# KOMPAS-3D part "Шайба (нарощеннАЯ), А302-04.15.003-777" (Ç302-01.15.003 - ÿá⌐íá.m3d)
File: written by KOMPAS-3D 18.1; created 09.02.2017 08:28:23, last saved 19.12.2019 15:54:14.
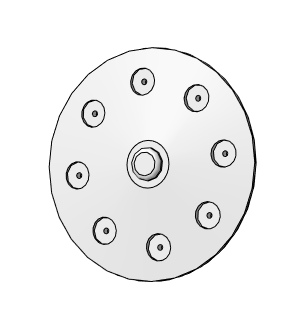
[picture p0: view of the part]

Document properties: Автор: Милов; Организация: Милов; Полное имя файла: D:\Мембранные насосы\Мембранный электропривод\А302-00.00.000 - ASTRA-302 (МЭ200)\3Д ПВХ\А302-01.15.003 - Шайба.m3d

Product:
- Part/product: Шайба (нарощеннАЯ)  | designation А302-04.15.003-777
    Материал: Полипропилен  ГОСТ 26996-86 (density 900 kg/m3)
    Масса: 0.433016
    Раздел спецификации: Детали
    Форматы листов документа: A4
    source file: ..\А302-04.00.000 - Мембранный насос ASTRA-302-PP\А302-04.15.003-777 - Шайба.cdw
- Part/product: Шайба  | designation А302-05.15.003
    Материал: Поливинилхлорид (density 0 kg/m3)
    Раздел спецификации: Детали
    Форматы листов документа: A4
    source file: ..\А302-04.00.000 - Мембранный насос ASTRA-302-PP\А302-04.15.003 - Шайба.cdw, ..\Чертежи ПВХ\А302-02.15.003 - Шайба.cdw, ..\Чертежи Полипропилен\А302-03.15.003 - Шайба.cdw
- Part/product: Шайба  | designation А302-01.15.003
    Масса: 0.292092
    Раздел спецификации: Детали
    Форматы листов документа: A4
- Part/product: Шайба  | designation А302-03.15.003
    Материал: Полипропилен  ГОСТ 26996-86 (density 900 kg/m3)
    Масса: 0.28231
    Раздел спецификации: Детали
    Форматы листов документа: A4
    source file: ..\Чертежи Полипропилен\А302-03.15.003 - Шайба.cdw
- Part/product: Шайба  | designation А302-02.15.003
    Материал: Полипропилен  ГОСТ 26996-86 (density 900 kg/m3)
    Масса: 0.251914
    Раздел спецификации: Детали
    Форматы листов документа: A4
- Part/product: Шайба  | designation А302-04.15.003
    Материал: Полипропилен  ГОСТ 26996-86 (density 900 kg/m3)
    Масса: 0.247573
    Раздел спецификации: Детали
    Форматы листов документа: A4

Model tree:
1. Эскиз:7
2. Операция вращения:1
     Угол 1 = 360
3. Скругление:16  (with: Операция вращения:1)
     Радиус = 4
4. Отверстие:1  (with: Операция вращения:1)
     Глубина выреза = 15; Диаметр отверстия = 7.8; Угол конуса торца = 118
5. Эскиз:22  (with: Операция вращения:1, Отверстие:1)
6. Отверстие:2
     Глубина выреза = 9; Диаметр отверстия = 6; Угол конуса торца = 118; Координата Y = -50
7. Массив по концентрической сетке:1  (with: Отверстие:2, Эскиз:22)  (4 pattern instances)
     Шаг 2 = 360
8. Эскиз:23
9. Отверстие:3
     Глубина выреза = 15; Диаметр отверстия = 5; Угол конуса торца = 118; Координата Y = 70
10. Эскиз:24  (with: Операция вращения:1)
11. Вырезать элемент выдавливания:3
     Расстояние 1 = 7.5
12. Массив по концентрической сетке:2  (with: Отверстие:3, Эскиз:23, Вырезать элемент выдавливания:3, Эскиз:24)  (6 pattern instances)
     Шаг 2 = 360
13. Фаска:1  (with: Отверстие:1)
     Угол = 45; Длина 1 = 1; Длина 2 = 1
14. Эскиз:25  (with: Операция вращения:1, Отверстие:1)
15. Операция выдавливания:1
     Расстояние 1 = 11
16. Условное изображение резьбы:1  (with: Операция выдавливания:1)
     Длина резьбы = 11; Шаг резьбы = 1.814; Номинальный диаметр резьбы = 20.955
17. Подгонка:1  (with: Операция выдавливания:1)
18. Фаска:2  (with: Операция выдавливания:1)  (labels: Полипропилен  ГОСТ 26996-86)
     Угол = 45; Длина 1 = 8; Длина 2 = 8
19. Скругление:17  (with: Операция вращения:1)
     Радиус = 4
20. Эскиз:26  (with: Операция вращения:1, Скругление:16)
21. Элемент выдавливания:1
     Расстояние 2 = 10
22. Скругление:18  (with: Элемент выдавливания:1)  (labels: Полипропилен  ГОСТ 26996-86)
     Радиус = 3
23. Отверстие:3  (with: Эскиз:23)
24. Вырезать элемент выдавливания:3  (with: Эскиз:23, Эскиз:24, Отверстие:3)  (1 pattern instances)
     N 1 = 1; Шаг 1 = 10; Шаг 2 = 360; Номер 1 = 1
25. Эскиз:27  (with: Операция вращения:1, Скругление:16)
26. Элемент выдавливания:3
     Расстояние 2 = 1
27. Эскиз:28  (with: Элемент выдавливания:3)
28. Элемент выдавливания:4
     Толщина стенки 1 = 2; Расстояние 1 = 1
29. Скругление:19  (with: Элемент выдавливания:4)
     Радиус = 1
30. Фаска:3  (with: Элемент выдавливания:3, Скругление:16)
     Угол = 15; Длина 1 = 13; Длина 2 = 3.48334
31. Скругление:20  (with: Фаска:3)
     Радиус = 2
32. Скругление:21  (with: Элемент выдавливания:4)  (labels: Полипропилен  ГОСТ 26996-86)
     Радиус = 0.5
33. Точка:1  (with: Операция вращения:1)
     X = 21
34. Параллельная плоскость:1  (with: Операция выдавливания:1, Эскиз:29, Скругление:3, Элемент выдавливания:1, Операция вращения:1, Вырезать элемент выдавливания:3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)  (labels: Каркас\Сталь 10  ГОСТ 1050-88; А302-01.00.000  - Мембранный насос ASTRA-302 ПВХ.a3d)
35. Элемент вращения:1  (with: Скругление:17)
     Угол 1 = 360
36. Эскиз:30  (with: Элемент вращения:1)
37. Элемент выдавливания:5
     Расстояние 2 = 32
38. Эскиз:31  (with: Элемент вращения:1)
39. Эскиз:32  (with: Вырезать элемент выдавливания:3)
40. Элемент выдавливания:6
     Расстояние 1 = 182
41. Эскиз:33  (with: Элемент выдавливания:6, Элемент вращения:1)
42. Эскиз:34  (with: Элемент вращения:1, Вырезать элемент выдавливания:3)  (labels: Полипропилен  ГОСТ 26996-86)

Expressions: (250-60)/2+3; G 1/2; cil2_6357-81
Referenced files in D:\Мембранные насосы\Мембранный электропривод\А302-00.00.000 - ASTRA-302 (МЭ200)\3Д ПВХ\: А302-01.00.000  - Мембранный насос ASTRA-302 ПВХ.a3d
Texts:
  Точка начала. Х
  Точка начала. Y
  Точка начала. Z
  Рабочая камера\Крышка рабочей камеры\Крышка\Крышка
  Рабочая камера\Крышка рабочей камеры\Крышка\Труба полипропиленовая 50*4,6

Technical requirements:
  Gost Type A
